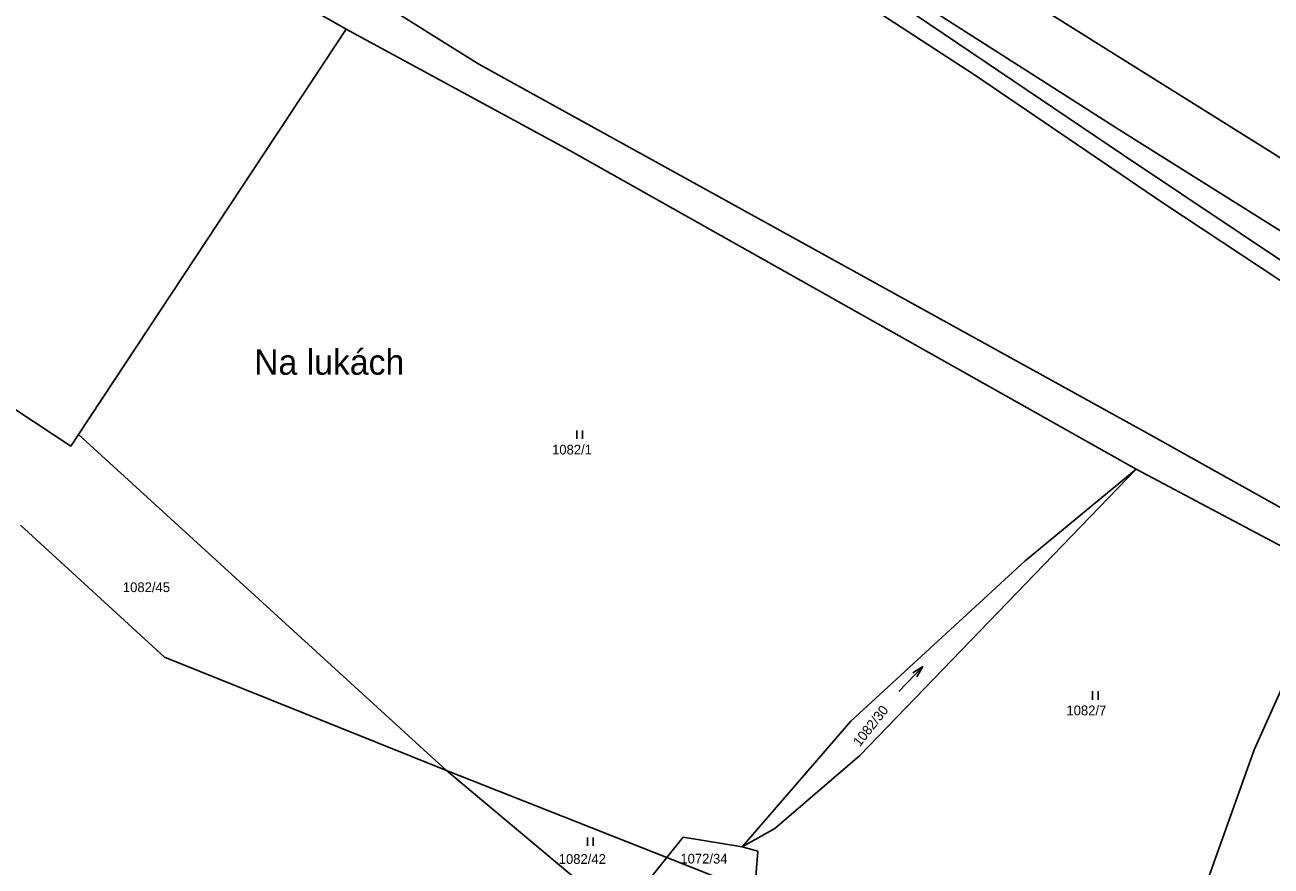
# Model space of a CAD drawing. Extents: x -852001 to -842497, y -1063614 to -1052182.
# Drawn here: x -849639.2 to -849422.1, y -1056170 to -1056023.5 of the extents above; entities that cross this region are included whole.
import ezdxf

# ---------------------------------------------------------------- set-up
doc = ezdxf.new("R2010")
doc.units = 0
for name, color, linetype in [('Default', 7, 'Continuous'), ('KN_HRANICE', 7, 'Continuous'), ('KN_KULTURY', 7, 'Continuous'), ('KN_PARCELY', 7, 'Continuous')]:
    doc.layers.add(name, color=color, linetype=linetype)

# ---------------------------------------------------------------- blocks, each defined once
blk = doc.blocks.new('306')
at = {"layer": 'Default'}
for p, q in [((-0.5, 1.5), (-0.5, 0)), ((0.5, 0), (0.5, 1.5))]:
    blk.add_line(p, q, dxfattribs=at)
blk = doc.blocks.new('802')
at = {"layer": 'Default'}
blk.add_line((-3, 0), (3, 0), dxfattribs=at)
blk.add_lwpolyline([(1, 0.5), (3, 0), (1, -0.5)], dxfattribs=at)

msp = doc.modelspace()

# ---------------------------------------------------------------- linework, layer by layer
at = {"layer": 'KN_HRANICE'}
for p, q in [((-849567.55, -1055954.51), (-849412.04, -1056051.96)), ((-849645.25, -1055988.73), (-849583.23, -1056024.23)), ((-849533.77, -1055987.36), (-849447.97, -1056042.09)), ((-849473.77, -1056032.19), (-849531.18, -1055994.73)), ((-849516.66, -1055999.69), (-849447.99, -1056046.05)), ((-849560.1, -1056030.34), (-849595.86, -1056007.92)), ((-849629.86, -1056094.78), (-849583.23, -1056024.23)), ((-849583.23, -1056024.23), (-849544.37, -1056045.31)), ((-849443.99, -1056094.41), (-849560.1, -1056030.34)), ((-849440.78, -1056054.56), (-849473.77, -1056032.19)), ((-849447.97, -1056042.09), (-849309.42, -1056129.11)), ((-849544.37, -1056045.31), (-849445.63, -1056100.85)), ((-849447.99, -1056046.05), (-849400.8, -1056077.65)), ((-849379.78, -1056094.91), (-849440.78, -1056054.56)), ((-849631.22, -1056096.84), (-849650.34, -1056084.27)), ((-849631.22, -1056096.84), (-849629.86, -1056094.78)), ((-849629.86, -1056094.78), (-849565.73, -1056153.32)), ((-849443.99, -1056094.41), (-849418.2, -1056108.82)), ((-849493.74, -1056150.69), (-849445.63, -1056100.85)), ((-849464.96, -1056116.83), (-849445.63, -1056100.85)), ((-849411.33, -1056119.03), (-849445.63, -1056100.85)), ((-849639.94, -1056110.6), (-849614.89, -1056133.59)), ((-849495.31, -1056144.7), (-849464.96, -1056116.83)), ((-849425.04, -1056149.71), (-849411.33, -1056119.03)), ((-849614.89, -1056133.59), (-849565.73, -1056153.32)), ((-849514.22, -1056166.62), (-849495.31, -1056144.7)), ((-849508.53, -1056163.41), (-849493.74, -1056150.69)), ((-849437.73, -1056185.24), (-849425.04, -1056149.71)), ((-849565.73, -1056153.32), (-849533.49, -1056180.31)), ((-849565.73, -1056153.32), (-849527.38, -1056168.45)), ((-849514.22, -1056166.62), (-849508.53, -1056163.41)), ((-849527.38, -1056168.45), (-849524.53, -1056164.91)), ((-849524.53, -1056164.91), (-849514.22, -1056166.62)), ((-849514.22, -1056166.62), (-849511.52, -1056167.35)), ((-849532.73, -1056175.12), (-849527.38, -1056168.45)), ((-849527.38, -1056168.45), (-849519.17, -1056171.69)), ((-849512.08, -1056174.78), (-849511.52, -1056167.35))]:
    msp.add_line(p, q, dxfattribs=at)

# ---------------------------------------------------------------- block references
at = {"layer": 'KN_KULTURY'}
for p in [(-849542.54, -1056095.59), (-849452.7, -1056141), (-849540.7, -1056166.46)]:
    msp.add_blockref('306', p, dxfattribs=at)
at = {"layer": 'KN_KULTURY', "rotation": 46.180398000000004}
msp.add_blockref('802', (-849484.85, -1056137.4), dxfattribs=at)

# ---------------------------------------------------------------- texts
at = {"layer": 'KN_PARCELY'}
for s, height, p in [('Na lukách', 4.4, (-849599.27, -1056084.4)), ('1082/1', 1.7, (-849547.36, -1056098.29)), ('1082/45', 1.7, (-849622.13, -1056122.25)), ('1082/7', 1.7, (-849457.76, -1056143.7)), ('1082/42', 1.7, (-849546.2, -1056169.58)), ('1072/34', 1.7, (-849525.01, -1056169.52))]:
    msp.add_text(s, height=height, dxfattribs=at).set_placement(p)
msp.add_text('1082/30', height=1.7, rotation=51.566, dxfattribs=at).set_placement((-849493.76, -1056149.28))

doc.saveas('drawing.dxf')
